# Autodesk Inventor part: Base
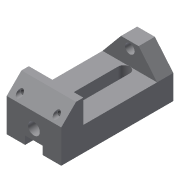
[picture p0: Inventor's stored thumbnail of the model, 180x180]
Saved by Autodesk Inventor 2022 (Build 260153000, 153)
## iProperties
Created: 2002-02
Part Number: Base
Document SubType Name: Modeling
Designer: ***
Density: 1 g/cm^3
Material: Generic
Appearance: Default
Control State: 0
Master: False
Checked Out: False
Shininess: 77.0
Length Units: 11269
Angle Units: 11279
Time Units: 11290
Mass Units: 11283
Length Display Precision: 3
Angle Display Precision: 2
Density: 0.0
Volumn: 0.0
Area: 0.0
PropertySet Name: Model Information
Author: ***
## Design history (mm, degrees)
sketch "Sketch2"
  geometry: L1 (-63.961, -4.254)-(-63.961, -37.254); L2 (-63.961, -37.254)-(88.039, -37.254); L3 (88.039, -37.254)-(88.039, 7.746); L4 (88.039, 7.746)-(68.039, 27.746); L5 (68.039, 27.746)-(58.039, 27.746); L6 (58.039, 27.746)-(58.039, -4.254); L7 (58.039, -4.254)-(-63.961, -4.254)
  constraints: 14 end point, 4 parallel, 1 perpendicular, 1 vertical
  dimensions: "d7" = 10 distance of L4.end L5.end; "d8" = 135 deg angle of L3 L4; "d9" = 33 distance of L1.start L1.end; "d10" = 152 distance of L1.end L2.end; "d11" = 65 distance between parallel lines of L5 L2; "d21" = 30 distance between parallel lines of L3 L6
extrude "Extrusion1" new body sketch "Sketch2" stored distance "d13" = 74; taper "d14" = 0 deg
sketch "Sketch3"
  geometry: L1 (0, 74)-(0, 0) reference; L2 (0, 0)-(-30, 25); L3 (-30, 25)-(-30, 49); L4 (-30, 49)-(0, 74); C1 r 6.5 at (-21, 37)
  constraints: 6 end point, 1 centre point, 1 equal length, 1 parallel
  dimensions: "d15" = 24 distance of L2.end L3.end; "d16" = 30 distance between parallel lines of L3 L1; "d17" = 13 diameter of C1; "d18" = 9 distance from line of L3 C1.centre
extrude "Extrusion2" join sketch "Sketch3" distance "d19" = 22; taper "d20" = 0 deg
sketch "Sketch4"
  geometry: L1 (0, 0)-(0, 74) reference; L2 (0, 0)-(45, 0) reference; C1 r 8 at (25, 37)
  constraints: 1 centre point
  dimensions: "d22" = 16 diameter of C1; "d23" = 25 distance from line of L1 C1.centre; "d24" = 37 distance from line of L2 C1.centre
extrude "Extrusion3" cut sketch "Sketch4" distance "d25" = 13; taper "d26" = 0 deg
sketch "Sketch5"
  geometry: L1 (45, 74)-(0, 74) reference; L2 (65, 0)-(65, 74) reference; 1 further point
  dimensions: "d27" = 12 distance from line of point (51, 62) L1; "d28" = 14 distance from line of L2 point (51, 62)
hole "Hole1" sketch "Sketch5" at (51, 62) diameter "d29" = 4.917; stored, may be unused: countersink angle "d33" = 82 deg, drill point angle "d35" = 0 deg; dims "d30" = 12, "d31" = 8, "d32" = 10, "d34" = 45
mirror "Mirror1"
sketch "Sketch6"
  geometry: L1 (100, 0)-(100, 74) reference; L2 (100, 74)-(0, 74) reference; L3 (14, 45)-(92, 45); L4 (92, 29)-(14, 29); A1 r 8 centre (92, 37) between (92, 29) and (92, 45); A2 r 8 centre (14, 37) between (14, 45) and (14, 29)
  constraints: 4 end point, 4 point on circle, 4 tangent, 2 centre point, 1 horizontal, 1 parallel
  dimensions: "d36" = 8 radius of A2; "d37" = 78 distance of L4.start L4.end; "d38" = 8 distance from line of L1 A1.centre; "d39" = 37 distance from line of L2 A2.centre
extrude "Extrusion4" cut sketch "Sketch6" extent not by distance; stored distance "d40" = 13; taper "d41" = 0 deg
sketch "Sketch7"
  geometry: L1 (45, 74)-(0, 74) reference; L2 (11, 49)-(0, 49); L3 (0, 49)-(0, 25); L4 (0, 25)-(11, 25); L5 (11, 25)-(11, 49); L6 (0, 0)-(45, 0) reference; L7 (0, 0)-(0, 74) reference
  constraints: 8 end point, 2 parallel, 1 collinear, 1 horizontal, 1 perpendicular
  dimensions: "d47" = 11 distance of L3.end L4.end; "d48" = 25 distance between parallel lines of L6 L4; "d49" = 24 distance of L2.end L3.end
extrude "Extrusion5" cut sketch "Sketch7" extent not by distance; stored distance "d45" = 13; taper "d46" = 0 deg
body "Solid1"
